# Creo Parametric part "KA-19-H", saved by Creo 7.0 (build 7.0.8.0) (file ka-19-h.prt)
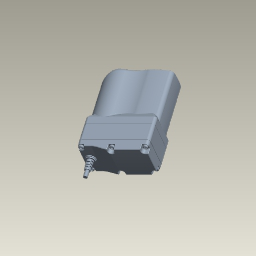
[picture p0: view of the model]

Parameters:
  PTC_COMMON_NAME = "ka-19-h.prt"
  PTC_WM_REVISION = "A"
  PTC_WM_ITERATION = "1"
  PTC_WM_VERSION = "A.1"
  PTC_WM_LIFECYCLE_STATE = "Concept"
  PTC_WM_LIFECYCLE = "Life Cycle Schema Type 1"
  PTC_WM_LOCATION = "/Products/KA19_CN2215/CAD"
  PTC_WM_CREATED_BY = "Jörg Monien"
  PTC_WM_CREATED_ON = "2026-08-11"
  PTC_WM_MODIFIED_BY = "Jörg Monien"
  PTC_WM_MODIFIED_ON = "2026-08-11"
  PTC_WM_NAME = "ka-19-h.prt"
  PTC_WM_NUMBER = "KA-19-H.PRT"
  PDMREV = "A.1+"
  PDMRL = "Concept"
  PROI_REVISION = "A"
  PROI_VERSION = "1"
  PROI_RELEASE = "Concept"

Other parameters: PROI_MODIFIED

Created from: 1079W4001-H.PRT

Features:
  1. datum plane "RIGHT"
  2. datum plane "TOP"
  3. datum plane "FRONT"
  4. coordinate system
  5. datum axis
  6. datum axis
  7. datum axis
  8. imported feature

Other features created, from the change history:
  feature "Copy Geometry id 76293"
  datum plane "DTM1" (2 times)
  cut "Trim 1" (2 times)
  fill "Fill 1" (2 times)
  feature "Merge 1" (2 times)
  patch "Solidify 1" (2 times)
  imported feature "Import Feature id 81822"
  feature "Copy Geometry id 82581"
  imported feature "Import Feature id 84558"
  datum plane "DTM2"
  sketch "Sketch 1"
  extrusion "Extrude 1" (2 times)
  extruded cut "Extrude 1"
  feature "Remove 1"

Other named items: X-AXES, Y-AXES, Z-AXES, CS0

Layers: ANNOTATIONS, AXES, COSMETICS, CSYS, CURVES, EXT_COPY_GEOM, PLANES, POINTS, PUBLISHED_GEOM, QUILTS, SOLIDS, STARTUP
